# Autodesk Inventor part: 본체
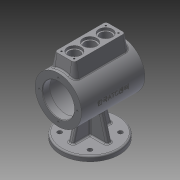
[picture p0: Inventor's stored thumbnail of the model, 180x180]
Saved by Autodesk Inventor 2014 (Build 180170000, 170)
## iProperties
Created: 2015-11
Part Number: 본체
Material: 일반
Document SubType Name: Modeling
Designer: mduedu
Density: 2.71 g/cm^3
Appearance: 기본값
Author: mduedu
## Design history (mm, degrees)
sketch "스케치2"
  geometry: C1 r 47.5 at (0, 0); 1 further point
  constraints: 1 centre point, 1 coincident
  dimensions: "d147" = 95 diameter of C1
extrude "돌출1" new body sketch "스케치2" stored distance "d12" = 130; taper "d13" = 0 deg
feature "쉘1" dims "d31" = 15, "d32" = 6, "d33" = 15
sketch "스케치5"
  geometry: C1 r 32.5 at (0, 0); 1 further point
  constraints: 1 centre point, 1 coincident
  dimensions: "d34" = 65 diameter of C1
extrude "돌출3" cut sketch "스케치5" stored distance "d36" = 3; taper "d37" = 0 deg
node "작업 평면1"
sketch "스케치6"
  geometry: L1 (-60, -55)-(60, -55); L2 (60, -55)-(60, 55); L3 (60, 55)-(-60, 55); L4 (-60, 55)-(-60, -55); L5 (-60, -55)-(60, 55); L6 (60, -55)-(-60, 55); C1 r 60 at (0, 0); 1 further point
  constraints: 12 end point, 2 midpoint, 2 parallel, 1 centre point, 1 coincident, 1 horizontal, 1 perpendicular
  dimensions: "d41" = 110 distance of L3.end L1.start; "d43" = 120 distance of L2.end L3.end; "d199" = 120 diameter of C1
extrude "돌출4" join sketch "스케치6" distance "d44" = 10; taper "d45" = 0 deg
sketch "스케치19"
  geometry: L1 (-5, 40)-(5, 40); L2 (5, 40)-(5, -40); L3 (5, -40)-(-5, -40); L4 (-5, -40)-(-5, 40); L5 (-60, 55)-(-60, -55) reference; L6 (5, -40)-(-5, 40); L7 (5, 40)-(-5, -40); 3 further points
  constraints: 12 end point, 2 midpoint, 2 parallel, 1 coincident, 1 horizontal, 1 horizontal alignment, 1 perpendicular
  dimensions: "d151" = 10 distance of L1.start L1.end; "d152" = 80 distance of L3.end L1.start
extrude "돌출9" join sketch "스케치19" stored distance "d153" = 10; taper "d154" = 0 deg
feature "면 기울기2" dims angle "d198" = 15 deg
sketch "스케치20"
  geometry: L1 (65, 32.5)-(50, 32.5) reference; L2 (50, 32.5)-(50, 41.5) reference; L3 (50, 41.5)-(-50, 41.5) reference; L4 (-50, 41.5)-(-50, 32.5) reference; L5 (-50, 32.5)-(-65, 32.5) reference; L6 (-65, 32.5)-(-65, 47.5) reference; L7 (-65, 47.5)-(65, 47.5) reference; L8 (65, 47.5)-(65, 32.5) reference; L9 (50, -32.5)-(65, -32.5) reference; L10 (65, -32.5)-(65, -47.5) reference; L11 (65, -47.5)-(5, -47.5) reference; L12 (5, -47.5)-(5, -90) reference; L13 (5, -90)-(60, -90) reference; L14 (60, -100)-(-60, -100) reference; L15 (-60, -90)-(-5, -90) reference; L16 (-5, -90)-(-5, -47.5) reference; L17 (-5, -47.5)-(-65, -47.5) reference; L18 (-65, -47.5)-(-65, -32.5) reference; L19 (-65, -32.5)-(-50, -32.5) reference; L20 (-50, -32.5)-(-50, -41.5) reference; L21 (-50, -41.5)-(50, -41.5) reference; L22 (50, -41.5)-(50, -32.5) reference; L23 (-40, -90)-(-28.612, -47.5); L24 (60, -90)-(60, -100) reference; L25 (-60, -100)-(-60, -90) reference; 1 further point
  constraints: 2 end point, 2 point on line
  dimensions: "d156" = 105 deg angle of L23 L15; "d200" = 20 distance from line of L23.start L25
feature "리브2" sketch "스케치20" dims "d157" = 1, "d158" = 10, "d159" = 0, "d160" = 0, "d161" = 1, "d162" = 1
fillet "모깎기21" dims "d163" = 3
fillet "모깎기22" dims "d164" = 3
fillet "모깎기23" dims "d165" = 3
sketch "스케치21" dims "d166" = 78
  geometry: 3 further points
  constraints: 2 horizontal alignment, 1 coincident, 2 other
hole "구멍6" sketch "스케치21" at (39, 0) diameter "d168" = 3.242; stored, may be unused: countersink angle "d172" = 90 deg, drill point angle "d174" = 118 deg; dims "d169" = 9, "d170" = 4, "d171" = 2, "d173" = 11
node "작업 평면2"
sketch "스케치13"
  geometry: L1 (-52.5, -20)-(52.5, -20); L2 (52.5, -20)-(52.5, 20); L3 (52.5, 20)-(-52.5, 20); L4 (-52.5, 20)-(-52.5, -20); L5 (-52.5, -20)-(52.5, 20); L6 (52.5, -20)-(-52.5, 20); 1 further point
  constraints: 12 end point, 2 midpoint, 2 parallel, 1 horizontal, 1 perpendicular
  dimensions: "d93" = 105 distance of L2.end L3.end; "d95" = 40 distance of L1.end L2.end
extrude "돌출8" join sketch "스케치13" stored distance "d96" = 80; taper "d97" = 0 deg
fillet "모깎기15" dims "d98" = 5
feature "면 기울기1" dims angle "d178" = 10 deg
fillet "모깎기24" dims "d179" = 3
sketch "스케치14"
  geometry: L1 (-52.5, 15)-(-52.5, -15) reference; L2 (52.5, -15)-(52.5, 15) reference; L3 (-52.5, 0)-(52.5, 0); 4 further points
  constraints: 2 end point, 2 midpoint, 2 point on line, 1 coincident
  dimensions: "d100" = 32 distance of point (-32, 0) point (0, 0); "d102" = 32 distance of point (32, 0) point (0, 0) (derived)
hole "구멍3" sketch "스케치14" at (-32, 0), (0, 0), (32, 0) diameter "d103" = 22; stored, may be unused: countersink angle "d107" = 90 deg, drill point angle "d109" = 118 deg; dims "d104" = 8, "d105" = 28, "d106" = 5, "d108" = 10
sketch "스케치15"
  geometry: L1 (45.5, -13)-(-45.5, -13); L2 (-45.5, -13)-(-45.5, 13); L3 (-45.5, 13)-(45.5, 13); L4 (45.5, 13)-(45.5, -13); L5 (45.5, -13)-(-45.5, 13); L6 (-45.5, -13)-(45.5, 13); L7 (47.5, 20)-(-47.5, 20) reference; L8 (-52.5, 15)-(-52.5, -15) reference; 5 further points
  constraints: 12 end point, 4 coincident, 2 midpoint, 2 parallel, 1 horizontal, 1 perpendicular
  dimensions: "d110" = 7 distance between parallel lines of L3 L7; "d111" = 7 distance between parallel lines of L2 L8 (derived)
hole "구멍4" sketch "스케치15" at (-45.5, 13), (45.5, 13), (45.5, -13), (-45.5, -13) diameter "d112" = 3.242; stored, may be unused: countersink angle "d116" = 90 deg, drill point angle "d118" = 118 deg; dims "d113" = 10, "d114" = 28, "d115" = 5, "d117" = 13
node "작업 평면3"
chamfer "모따기2" distance "d183" = 1; stored, may be unused: second distance "d184" = 2, angle "d185" = 45 deg
fillet "모깎기26" dims "d194" = 3
sketch "스케치24"
  geometry: L1 (-31.113, -31.113)-(31.113, -31.113); L2 (31.113, -31.113)-(31.113, 31.113); L3 (31.113, 31.113)-(-31.113, 31.113); L4 (-31.113, 31.113)-(-31.113, -31.113); L5 (-31.113, -31.113)-(31.113, 31.113); L6 (31.113, -31.113)-(-31.113, 31.113); 1 further point
  constraints: 12 end point, 2 midpoint, 2 parallel, 2 perpendicular, 1 horizontal
  dimensions: "d201" = 88 distance of L1.start L2.end
hole "구멍8" sketch "스케치24" at (-31.113, -31.113), (31.113, 31.113), (31.113, -31.113), (-31.113, 31.113) diameter "d203" = 9; stored, may be unused: countersink angle "d207" = 90 deg, drill point angle "d209" = 118 deg; dims "d204" = 6, "d205" = 4, "d206" = 2, "d208" = 8
sketch "스케치22"
  geometry: 2 further points
  constraints: 1 coincident, 1 other
feature "엠보싱3" sketch "스케치22" dims "d31" = 15, "d93" = 105, "d95" = 40, "d181" = 0.5, "d182" = 0
node "솔리드1"
mirror "대칭6"
pattern_circular "원형 패턴2" dims angle "d176" = 360 deg
mirror "대칭5"
node "절단 모서리 투영1"
